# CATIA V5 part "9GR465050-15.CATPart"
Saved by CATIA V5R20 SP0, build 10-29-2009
Part number: 9GR465050-15
Revision: ANY
Definition: UNKNOWN
Nomenclature: 9GR465050-15
Source: Unknown
Bounding box of the stored display mesh (mm): x -24.999 to 24.818, y -45 to 5, z -25 to 25
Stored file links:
  C:\Users\Utente\Desktop\IO LAVORO\3D X SITO CF\CUMSA\3D files GR\GR 465050-15\9GR465050-15.CATPart
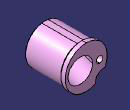
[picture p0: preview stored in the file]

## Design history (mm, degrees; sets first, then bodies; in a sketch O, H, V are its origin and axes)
Body1 "Cortar-Extruir7" (main body)
  Solid1: solid without history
